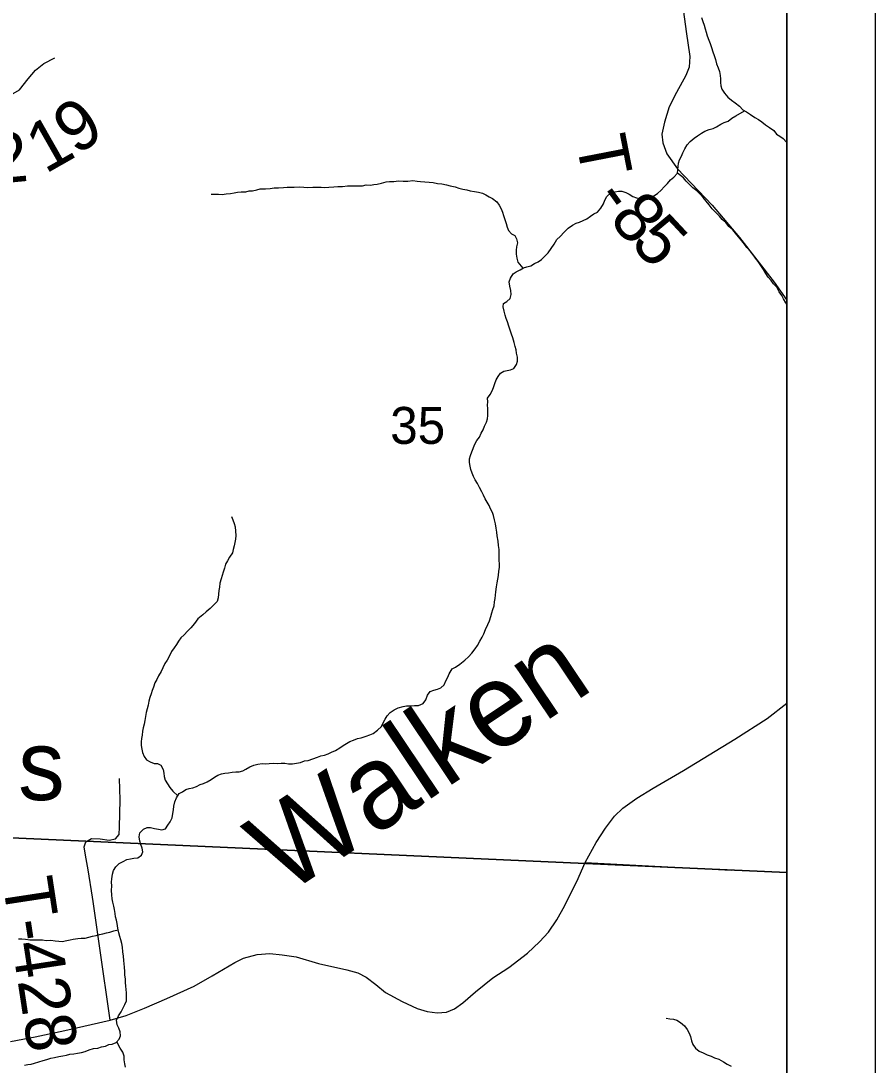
# Model space of a CAD drawing. Extents: x -20.2 to 34, y 0 to 22.
# Drawn here: x 8.033 to 9, y 16.636 to 17.818 of the extents above; entities that cross this region are included whole.
import ezdxf

# ---------------------------------------------------------------- set-up
doc = ezdxf.new("R2010")
doc.units = 0
for name, color, linetype in [('Default', 7, 'Continuous'), ('GM_X_County_Road', 7, 'Continuous'), ('GM_X_Minor_River', 7, 'Continuous'), ('GM_X_Minor_River_Text', 7, 'Continuous'), ('GM_X_Section_Text', 7, 'Continuous'), ('GM_X_Township_Road', 7, 'Continuous'), ('GM_X_Township_Road_Text', 7, 'Continuous'), ('GM_X_Unincorporated_Text', 7, 'Continuous'), ('SH_Cut_Line', 7, 'Continuous'), ('SH_Data', 7, 'Continuous')]:
    doc.layers.add(name, color=color, linetype=linetype)

msp = doc.modelspace()

# ---------------------------------------------------------------- linework, layer by layer
at = {"layer": 'Default'}
msp.add_lwpolyline([(8.9, 14.8176), (8.9, 20.9), (8.1508, 20.9), (8.1316, 20.5548), (8.0709, 19.4522), (8.0485, 19.0914), (8.043, 18.9097), (7.8072, 18.9199), (7.5395, 18.9382), (7.3871, 18.9465), (6.5332, 18.9927), (5.9006, 19.026), (5.871, 18.5384), (5.8069, 17.4844), (5.7831, 17.2483), (5.7812, 17.1527), (5.7368, 16.4206)], dxfattribs=at)
for points in [[(8.9, 16.8537), (8.9, 17.8451), (7.9819, 17.9077), (7.92, 16.8975)], [(8.9, 15.8211), (8.9, 16.8537), (7.92, 16.8975), (7.8624, 15.8798)]]:
    msp.add_lwpolyline(points, close=True, dxfattribs=at)
at = {"layer": 'GM_X_County_Road'}
msp.add_lwpolyline([(8.0207, 16.6622), (8.0486, 16.6675), (8.0822, 16.675), (8.1338, 16.6867), (8.1516, 16.6918), (8.1725, 16.7002), (8.1979, 16.711), (8.2287, 16.7249), (8.2491, 16.7367), (8.2748, 16.7518), (8.2846, 16.7569), (8.3002, 16.7609), (8.3146, 16.7621), (8.3285, 16.7605), (8.3441, 16.7581), (8.3694, 16.7508), (8.4018, 16.7434), (8.4143, 16.74), (8.4234, 16.7352), (8.4347, 16.7268), (8.4455, 16.718), (8.4644, 16.7075), (8.4812, 16.6997), (8.4928, 16.6963), (8.5038, 16.6949), (8.5144, 16.6956), (8.5235, 16.6992), (8.5331, 16.7062), (8.5473, 16.7187), (8.567, 16.7343), (8.5852, 16.7463), (8.6063, 16.7626), (8.6198, 16.7751), (8.6301, 16.7864), (8.6397, 16.8001), (8.6486, 16.8164), (8.6551, 16.8298), (8.662, 16.8435), (8.6716, 16.8651), (8.6841, 16.8879), (8.6947, 16.904), (8.705, 16.9175), (8.7144, 16.9268), (8.73, 16.9381), (8.7487, 16.9494), (8.7828, 16.9693), (8.8412, 17.0049), (8.8777, 17.0282), (8.9, 17.0457)], dxfattribs=at)
at = {"layer": 'GM_X_Minor_River'}
for points in [[(8.8032, 17.8224), (8.8047, 17.8179), (8.8063, 17.8137), (8.8075, 17.8096), (8.8087, 17.8058), (8.8099, 17.8016), (8.8115, 17.7967), (8.813, 17.7929), (8.8146, 17.7884), (8.8162, 17.7835), (8.8177, 17.7793), (8.8193, 17.7748), (8.8205, 17.7698), (8.8221, 17.7653), (8.8236, 17.7611)], [(8.8236, 17.7611), (8.8244, 17.7566), (8.8249, 17.7528), (8.8249, 17.7486), (8.8253, 17.7448), (8.8265, 17.741), (8.8296, 17.7365), (8.8331, 17.732), (8.8373, 17.7286), (8.8415, 17.7257), (8.8465, 17.7219), (8.85, 17.7178), (8.8545, 17.7156), (8.8588, 17.7126), (8.8637, 17.7092), (8.8679, 17.7066), (8.8718, 17.704), (8.876, 17.7006), (8.8802, 17.6976), (8.8852, 17.6943), (8.8882, 17.6901), (8.8921, 17.6879), (8.8959, 17.6853), (8.8997, 17.6812), (8.9, 17.681)], [(8.786, 17.6368), (8.7829, 17.6406), (8.776, 17.6458), (8.7774, 17.6572), (8.7785, 17.661), (8.7807, 17.6652), (8.7822, 17.6691), (8.7844, 17.6736), (8.787, 17.6779), (8.7904, 17.6817), (8.7949, 17.6856), (8.7987, 17.6883), (8.8032, 17.6914), (8.8073, 17.6937), (8.8119, 17.6956), (8.8164, 17.6965), (8.8202, 17.6984), (8.8251, 17.7015), (8.8292, 17.7035), (8.8334, 17.705), (8.8379, 17.7081), (8.8424, 17.7108), (8.8522, 17.7167)], [(8.2479, 17.6221), (8.2525, 17.6221), (8.2563, 17.6222), (8.2605, 17.6218), (8.265, 17.6227), (8.2699, 17.6231), (8.2741, 17.6235), (8.2779, 17.6243), (8.2821, 17.6248), (8.2874, 17.6248), (8.2912, 17.626), (8.2949, 17.6261), (8.2999, 17.6269), (8.3037, 17.6281), (8.3097, 17.6282), (8.3147, 17.6286), (8.3192, 17.6294), (8.3241, 17.6295), (8.3298, 17.6299), (8.334, 17.63), (8.3382, 17.63), (8.342, 17.6301), (8.3477, 17.6305), (8.353, 17.6302), (8.3575, 17.6299), (8.3632, 17.63), (8.3685, 17.63), (8.3727, 17.6301), (8.3769, 17.6298), (8.3811, 17.6302), (8.3871, 17.6303), (8.3913, 17.6307), (8.3966, 17.6308), (8.4023, 17.6316), (8.4061, 17.6317), (8.4107, 17.6317), (8.4156, 17.6318), (8.4194, 17.6318), (8.4235, 17.6326), (8.4285, 17.6323), (8.4323, 17.6331), (8.4361, 17.6336), (8.441, 17.6348), (8.4463, 17.636), (8.4501, 17.6364), (8.455, 17.6365), (8.4603, 17.6373), (8.4653, 17.637), (8.4709, 17.637), (8.4763, 17.6375), (8.4812, 17.6368), (8.485, 17.6364), (8.4899, 17.6361), (8.4949, 17.6358), (8.4994, 17.6355), (8.5044, 17.6344), (8.5093, 17.6337), (8.5146, 17.6326), (8.5188, 17.6316), (8.5245, 17.6305), (8.5284, 17.629), (8.5329, 17.6279), (8.5375, 17.6272), (8.5413, 17.6261), (8.5462, 17.6251), (8.5508, 17.6244), (8.5554, 17.6233), (8.5592, 17.6214), (8.563, 17.6192), (8.5668, 17.6173), (8.5714, 17.6136), (8.5741, 17.6098), (8.5765, 17.6057), (8.578, 17.6019), (8.5792, 17.5981), (8.5808, 17.5936), (8.582, 17.589), (8.5832, 17.5849), (8.5847, 17.5811), (8.5882, 17.5773), (8.592, 17.5755), (8.5939, 17.5717), (8.5948, 17.5672), (8.594, 17.5626), (8.5933, 17.5588), (8.5934, 17.5542), (8.5942, 17.5497), (8.5954, 17.5451), (8.601, 17.5382)], [(8.6223, 17.5481), (8.6261, 17.552), (8.6298, 17.5558), (8.6332, 17.5608), (8.6365, 17.5654), (8.6395, 17.5708), (8.6433, 17.5742), (8.6478, 17.5792), (8.6523, 17.5835), (8.6572, 17.5869), (8.6613, 17.5893), (8.6651, 17.5905), (8.6692, 17.5924), (8.6734, 17.5944), (8.6775, 17.5971), (8.6813, 17.5998), (8.6854, 17.6017), (8.6892, 17.6063), (8.6922, 17.6113), (8.694, 17.6155), (8.6962, 17.6197), (8.7008, 17.6236), (8.7053, 17.6248), (8.7095, 17.6256), (8.7133, 17.6256), (8.7178, 17.6242), (8.7216, 17.6223), (8.7255, 17.6197), (8.7297, 17.6179), (8.7339, 17.6168), (8.7377, 17.6164), (8.7414, 17.6176), (8.7452, 17.6181), (8.7494, 17.6204), (8.7535, 17.6231), (8.7577, 17.6266), (8.761, 17.6304), (8.7648, 17.6343), (8.7681, 17.6385), (8.7719, 17.6416), (8.776, 17.6458)], [(8.9, 17.4969), (8.8988, 17.4992), (8.8961, 17.5037), (8.8942, 17.5075), (8.8915, 17.5116), (8.8888, 17.5169), (8.8849, 17.5207), (8.8822, 17.5244), (8.8788, 17.5282), (8.8764, 17.5323), (8.8737, 17.5369), (8.8706, 17.5414), (8.8675, 17.5459), (8.8645, 17.5497), (8.8618, 17.5534), (8.8587, 17.5572), (8.8548, 17.5617), (8.8521, 17.5655), (8.849, 17.5692), (8.8452, 17.5737), (8.8417, 17.5779), (8.8387, 17.5816), (8.8344, 17.5857), (8.831, 17.5899), (8.8267, 17.5933), (8.8237, 17.5974), (8.8198, 17.6011), (8.8156, 17.6056), (8.8121, 17.6102), (8.8087, 17.6143), (8.8052, 17.6184), (8.8017, 17.6222), (8.7979, 17.6259), (8.7937, 17.6293), (8.7898, 17.6331), (8.786, 17.6368)], [(8.567, 17.1516), (8.5685, 17.1558), (8.5688, 17.1603), (8.5695, 17.1641), (8.5702, 17.1679), (8.5705, 17.1718), (8.5712, 17.1775), (8.5719, 17.182), (8.5727, 17.1862), (8.5734, 17.1904), (8.5737, 17.1953), (8.5744, 17.1992), (8.5744, 17.203), (8.5743, 17.2075), (8.5742, 17.2143), (8.5742, 17.2197), (8.5733, 17.2242), (8.5729, 17.2291), (8.5721, 17.2352), (8.5717, 17.2394), (8.5708, 17.2439), (8.57, 17.2489), (8.5688, 17.2534), (8.5676, 17.258), (8.5668, 17.2617), (8.5645, 17.2659), (8.5629, 17.2697), (8.5606, 17.2734), (8.5583, 17.2772), (8.5564, 17.2814), (8.5544, 17.2851), (8.5521, 17.29), (8.5497, 17.2946), (8.547, 17.2987), (8.5451, 17.3025), (8.5435, 17.3063), (8.5423, 17.3104), (8.5412, 17.3142), (8.5407, 17.3184), (8.5407, 17.3222), (8.5418, 17.326), (8.5433, 17.3302), (8.5447, 17.334), (8.5462, 17.3382), (8.5488, 17.3432), (8.5518, 17.347), (8.554, 17.3516), (8.5562, 17.3554), (8.5577, 17.3593), (8.5599, 17.3638), (8.561, 17.3677), (8.5614, 17.3715), (8.5613, 17.3753), (8.5613, 17.3794), (8.5609, 17.3832), (8.5612, 17.387), (8.5611, 17.3912), (8.5641, 17.3954), (8.5664, 17.3993), (8.5678, 17.4031), (8.5693, 17.4077), (8.5708, 17.4119), (8.573, 17.4157), (8.5756, 17.4195), (8.5794, 17.4215), (8.5832, 17.4226), (8.587, 17.4231), (8.5907, 17.4246), (8.5937, 17.4292), (8.5948, 17.4331), (8.5948, 17.4376), (8.5939, 17.4422), (8.5935, 17.4459), (8.5923, 17.4497), (8.5911, 17.4543), (8.5896, 17.4596), (8.588, 17.4637), (8.5868, 17.4683), (8.5852, 17.4728), (8.5837, 17.4774), (8.5821, 17.4815), (8.5809, 17.4853), (8.5797, 17.4898), (8.5789, 17.4944), (8.5792, 17.4982), (8.583, 17.5005), (8.5868, 17.504), (8.5878, 17.5086), (8.5874, 17.5131), (8.5862, 17.518), (8.5854, 17.523), (8.5869, 17.5272), (8.5899, 17.5318), (8.5936, 17.5341), (8.5981, 17.5364), (8.6019, 17.5388), (8.6057, 17.5399), (8.6099, 17.5411), (8.6144, 17.5435), (8.6185, 17.5454), (8.6223, 17.5481)], [(8.2712, 17.2569), (8.2724, 17.2531), (8.2739, 17.2493), (8.2751, 17.2452), (8.2756, 17.2406), (8.276, 17.2357), (8.2757, 17.2315), (8.275, 17.2277), (8.2742, 17.2239), (8.2731, 17.2197), (8.2721, 17.2159), (8.2687, 17.2109), (8.2665, 17.2067), (8.2642, 17.2029), (8.2631, 17.1987), (8.2617, 17.1941), (8.2606, 17.1903), (8.2595, 17.1865), (8.258, 17.1815), (8.2573, 17.1769), (8.2566, 17.1731), (8.2563, 17.1689), (8.256, 17.1648), (8.2549, 17.1609), (8.2511, 17.1571), (8.247, 17.1529), (8.2425, 17.149), (8.2387, 17.1455), (8.2331, 17.1413), (8.229, 17.1359), (8.2248, 17.1309), (8.2211, 17.1271), (8.2173, 17.1232), (8.2136, 17.1198), (8.211, 17.1159), (8.2087, 17.1121), (8.2061, 17.1083), (8.2031, 17.1041), (8.2009, 17.0991), (8.1983, 17.0945), (8.1957, 17.0907), (8.1931, 17.0857), (8.1913, 17.0815), (8.1883, 17.0765), (8.1864, 17.0723), (8.1842, 17.0685), (8.1827, 17.0639), (8.1813, 17.0601), (8.1802, 17.0563), (8.1787, 17.0521), (8.1776, 17.0479), (8.1765, 17.0433), (8.1754, 17.0391), (8.1743, 17.035), (8.1736, 17.0304), (8.1729, 17.0258), (8.1722, 17.022), (8.1711, 17.0178), (8.1704, 17.014), (8.1697, 17.0094), (8.169, 17.0056), (8.1687, 17.0018), (8.1687, 16.9977), (8.1695, 16.9935), (8.1703, 16.9897), (8.1723, 16.9852), (8.1746, 16.9814), (8.1788, 16.9792), (8.1834, 16.9773), (8.1872, 16.9774), (8.191, 16.9755), (8.1937, 16.9706), (8.1945, 16.9665), (8.1949, 16.9627), (8.1961, 16.9585), (8.1984, 16.9543), (8.2011, 16.9502), (8.2046, 16.9461), (8.2102, 16.9406)], [(8.2016, 16.9111), (8.2038, 16.9157), (8.2045, 16.9206), (8.2052, 16.9248), (8.2056, 16.929), (8.207, 16.9339), (8.2089, 16.9385), (8.2119, 16.9431), (8.2156, 16.9451), (8.2194, 16.9478), (8.2232, 16.949), (8.2273, 16.9498), (8.2315, 16.9513), (8.2357, 16.9533), (8.2394, 16.9545), (8.2436, 16.9564), (8.2481, 16.9592), (8.2519, 16.9619), (8.2556, 16.9642), (8.2598, 16.9654), (8.2636, 16.9662), (8.2678, 16.9666), (8.2719, 16.9674), (8.2761, 16.9679), (8.2799, 16.9679), (8.2837, 16.9691), (8.2874, 16.9707), (8.292, 16.9734), (8.2965, 16.9753), (8.3007, 16.9765), (8.3056, 16.9773), (8.3098, 16.977), (8.3136, 16.9774), (8.3181, 16.9775), (8.3227, 16.9772), (8.3272, 16.9776), (8.3314, 16.9777), (8.3356, 16.977), (8.3401, 16.977), (8.3447, 16.9778), (8.3492, 16.9783), (8.3538, 16.9802), (8.3579, 16.9807), (8.3632, 16.9826), (8.3685, 16.9846), (8.3723, 16.9858), (8.3765, 16.9866), (8.3806, 16.9882), (8.3844, 16.9901), (8.3889, 16.9921), (8.3938, 16.9952), (8.3976, 16.9975), (8.4014, 16.9998), (8.4051, 17.0021), (8.4093, 17.0037), (8.4138, 17.0057), (8.418, 17.0065), (8.4237, 17.0081), (8.4278, 17.0097), (8.4316, 17.0112), (8.4365, 17.0151), (8.441, 17.0193), (8.4428, 17.0235), (8.4451, 17.0273), (8.4473, 17.0312), (8.4507, 17.035), (8.4552, 17.0381), (8.4597, 17.0404), (8.4654, 17.042), (8.4692, 17.0425), (8.4741, 17.0425), (8.4783, 17.043), (8.4829, 17.043), (8.4881, 17.0454), (8.4911, 17.0492), (8.493, 17.0545), (8.496, 17.0588), (8.5001, 17.0603), (8.5043, 17.0615), (8.508, 17.0631), (8.5118, 17.0662), (8.5137, 17.0708), (8.5159, 17.075), (8.5177, 17.0788), (8.5211, 17.0845), (8.5249, 17.0865), (8.5298, 17.0896), (8.5354, 17.0942), (8.5395, 17.098), (8.5433, 17.1023), (8.547, 17.1073), (8.5496, 17.1111), (8.5522, 17.1157), (8.5548, 17.1203), (8.5567, 17.1241), (8.5589, 17.1291), (8.5615, 17.1348), (8.5633, 17.139), (8.5648, 17.1436), (8.5659, 17.1478), (8.567, 17.1516)], [(8.0367, 16.6355), (8.0405, 16.6363), (8.0442, 16.6368), (8.048, 16.638), (8.0529, 16.6395), (8.0579, 16.6407), (8.062, 16.6419), (8.0666, 16.6435), (8.0707, 16.6443), (8.0753, 16.6455), (8.0802, 16.6463), (8.084, 16.6468), (8.0878, 16.6479), (8.0923, 16.6484), (8.0965, 16.6492), (8.101, 16.65), (8.1052, 16.6512), (8.1097, 16.6528), (8.1146, 16.6544), (8.1196, 16.6548), (8.1237, 16.6564), (8.1283, 16.6572), (8.132, 16.6588), (8.1358, 16.6592), (8.1404, 16.6611), (8.1437, 16.665), (8.1452, 16.6688), (8.1448, 16.6734), (8.1436, 16.6775), (8.1417, 16.6813), (8.1408, 16.6866), (8.1431, 16.6916), (8.146, 16.6958), (8.1479, 16.6996), (8.1501, 16.7042), (8.152, 16.7084), (8.1523, 16.7133), (8.1522, 16.7175), (8.1518, 16.7213), (8.1514, 16.7251), (8.151, 16.7293), (8.1509, 16.7334), (8.1501, 16.7376), (8.1501, 16.7418), (8.15, 16.7467), (8.1496, 16.7505), (8.1492, 16.7543), (8.1487, 16.7589), (8.1479, 16.7638), (8.1475, 16.7691), (8.147, 16.7733), (8.1458, 16.7774), (8.1447, 16.7812), (8.1435, 16.7854), (8.1423, 16.7907), (8.1415, 16.796), (8.1407, 16.7998), (8.1398, 16.8036), (8.1394, 16.8074), (8.1386, 16.8119), (8.1378, 16.8157), (8.1366, 16.8202), (8.1358, 16.824), (8.1354, 16.8286), (8.1353, 16.8335), (8.1356, 16.8388), (8.1352, 16.843), (8.1355, 16.8468), (8.1362, 16.8518), (8.1373, 16.856), (8.1399, 16.8602), (8.1437, 16.864), (8.1482, 16.8664), (8.1524, 16.8687), (8.1565, 16.8691), (8.1603, 16.8699), (8.1649, 16.8704), (8.169, 16.8734), (8.1705, 16.8773), (8.1697, 16.8814), (8.1685, 16.8856), (8.1673, 16.8894), (8.1665, 16.8943), (8.1672, 16.8989), (8.1713, 16.9027), (8.1755, 16.9047), (8.1793, 16.9047), (8.1838, 16.9036), (8.1884, 16.9029), (8.1922, 16.9022), (8.1964, 16.9034), (8.199, 16.9073), (8.2016, 16.9111)], [(8.0919, 16.7783), (8.0969, 16.7791), (8.1007, 16.7795), (8.1052, 16.7796), (8.1094, 16.7804), (8.1135, 16.7816), (8.1177, 16.7824), (8.1215, 16.7836), (8.1253, 16.7844), (8.1294, 16.7856), (8.1332, 16.7864), (8.1378, 16.7876), (8.1427, 16.7889)], [(8.0297, 16.7786), (8.0335, 16.7787), (8.0377, 16.7784), (8.0426, 16.7777), (8.0479, 16.7777), (8.0525, 16.7774), (8.057, 16.7775), (8.0612, 16.7768), (8.0665, 16.7772), (8.0715, 16.7765), (8.0753, 16.7762), (8.0791, 16.7758), (8.0844, 16.7767), (8.0882, 16.7775), (8.0919, 16.7783)], [(8.7633, 16.6887), (8.7675, 16.688), (8.7717, 16.6877), (8.7755, 16.6866), (8.7797, 16.684), (8.7843, 16.6802), (8.787, 16.6761), (8.7893, 16.6719), (8.7909, 16.6682), (8.7921, 16.6632), (8.7937, 16.6591), (8.7964, 16.6549), (8.8006, 16.6516), (8.8052, 16.6494), (8.8097, 16.6471), (8.8143, 16.6457), (8.8181, 16.6438), (8.8231, 16.6424), (8.8284, 16.6394), (8.8326, 16.6368), (8.8368, 16.6346)], [(8.1509, 16.6332), (8.1501, 16.637), (8.1493, 16.6415), (8.1493, 16.6457), (8.1481, 16.6502), (8.145, 16.6547), (8.1412, 16.6621)]]:
    msp.add_lwpolyline(points, dxfattribs=at)
at = {"layer": 'GM_X_Township_Road'}
msp.add_line((8.6716, 16.8651), (8.8371, 16.8565), dxfattribs=at)
for points in [[(8.7797, 17.8541), (8.7859, 17.8066), (8.79, 17.778), (8.7893, 17.766), (8.7855, 17.7567), (8.7751, 17.7372), (8.7667, 17.7211), (8.7614, 17.7036), (8.7586, 17.6901), (8.7595, 17.6805), (8.7641, 17.6678), (8.7763, 17.6508), (8.8155, 17.6097), (8.8464, 17.5732), (8.8858, 17.5225), (8.9, 17.5021)], [(7.9887, 17.7321), (8.009, 17.7329), (8.0212, 17.7346), (8.0309, 17.7404), (8.0408, 17.7529), (8.0492, 17.7628), (8.0586, 17.7703), (8.0711, 17.7767)], [(8.1136, 16.8257), (8.1086, 16.8567), (8.1057, 16.8733), (8.1043, 16.8827), (8.1062, 16.8887), (8.1124, 16.8925), (8.1223, 16.8918), (8.1324, 16.8904), (8.1398, 16.892), (8.1437, 16.8968), (8.1442, 16.9053), (8.1449, 16.9362), (8.1442, 16.9604)], [(8.1338, 16.6867), (8.122, 16.7681), (8.1144, 16.821), (8.1136, 16.8257)]]:
    msp.add_lwpolyline(points, dxfattribs=at)
at = {"layer": 'SH_Cut_Line'}
msp.add_lwpolyline([(5.7735, 14.1), (8.9, 14.1), (8.9, 20.9), (2.1, 20.9), (2.1, 14.1), (5.3953, 14.1), (5.7268, 14.1076)], close=True, dxfattribs=at)
at = {"layer": 'SH_Data'}
for p, q in [((9, 21), (9, 14)), ((8.9, 20.9), (8.9, 14.1))]:
    msp.add_line(p, q, dxfattribs=at)

# ---------------------------------------------------------------- texts
at = {"layer": 'GM_X_Minor_River_Text'}
msp.add_text('Walken', height=0.09469, rotation=33.8591, dxfattribs=at).set_placement((8.3325, 16.8271))
at = {"layer": 'GM_X_Section_Text'}
msp.add_text('35', height=0.04186, rotation=0, dxfattribs=at).set_placement((8.4508, 17.3393))
at = {"layer": 'GM_X_Township_Road_Text'}
for s, height, rotation, p in [('9', 0.0568, 35.2811, (8.0956, 17.6651)), ('1', 0.0568, 29.6464, (8.0601, 17.6446)), ('2', 0.0568, 5.4187, (8.0004, 17.6334)), ('T', 0.0568, 280.978, (8.6608, 17.6831)), ('-', 0.0568, 305.7765, (8.6795, 17.6169)), ('8', 0.0568, 312.0176, (8.6973, 17.5927)), ('5', 0.0568, 313.069, (8.7215, 17.5659)), ('T-428', 0.05682, 278.6789, (8.0115, 16.844))]:
    msp.add_text(s, height=height, rotation=rotation, dxfattribs=at).set_placement(p)
at = {"layer": 'GM_X_Unincorporated_Text'}
msp.add_text('Flatwoods', height=0.07898, rotation=0, dxfattribs=at).set_placement((7.6008, 16.9359))

doc.saveas('drawing.dxf')
